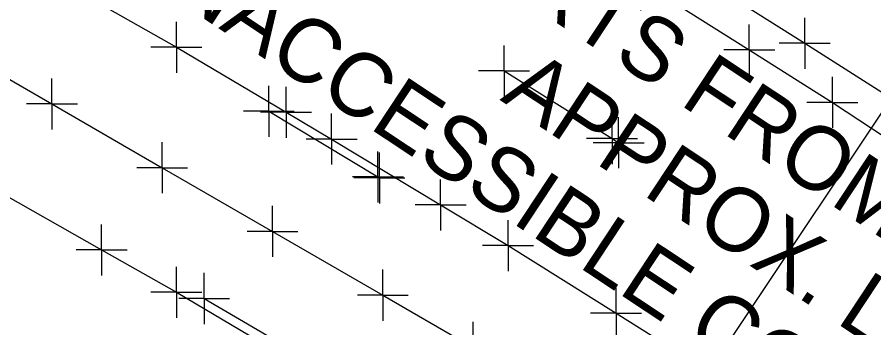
# Model space of a CAD drawing. Extents: x 0 to 1944463, y 0 to 420651.
# Drawn here: x 1942824.6 to 1942891.8, y 417789.8 to 417814.1 of the extents above; entities that cross this region are included whole.
import ezdxf

# ---------------------------------------------------------------- set-up
doc = ezdxf.new("R2010")
doc.units = 0
for name, color, linetype in [('SUR - DRG - Storm Sewer Text', 7, 'Continuous'), ('SUR - DTM - Breaklines', 7, 'Continuous'), ('SUR - DTM - Breaklines - Points - Locators', 7, 'Continuous'), ('SUR - TR-CTRL - Pavement Marking', 7, 'Continuous'), ('SUR - TR-CTRL - Pavement Marking - Points - Locators', 7, 'Continuous'), ('SUR - TRAN - Features', 7, 'Continuous'), ('SUR - UTL - Overhead Wire Crossings', 7, 'Continuous')]:
    doc.layers.add(name, color=color, linetype=linetype)

msp = doc.modelspace()

# ---------------------------------------------------------------- linework, layer by layer
at = {"layer": 'SUR - DTM - Breaklines'}
msp.add_lwpolyline([(1942706.496, 417864.602), (1942715.785, 417860.899), (1942725.074, 417857.195), (1942728.142, 417855.972), (1942737.3, 417851.955), (1942746.457, 417847.938), (1942755.615, 417843.922), (1942764.773, 417839.905), (1942767.692, 417838.624), (1942776.578, 417834.037), (1942785.464, 417829.45), (1942794.35, 417824.864), (1942803.236, 417820.277), (1942812.122, 417815.69), (1942818.635, 417812.328), (1942827.298, 417807.331), (1942835.96, 417802.335), (1942844.622, 417797.339), (1942853.285, 417792.343), (1942860.379, 417788.251), (1942868.814, 417782.88), (1942877.25, 417777.509), (1942885.685, 417772.138), (1942894.12, 417766.767)], dxfattribs=at)
at = {"layer": 'SUR - DTM - Breaklines - Points - Locators'}
for p, q in [((1942827.298, 417807.331), (1942827.298, 417809.331)), ((1942827.298, 417807.331), (1942825.298, 417807.331)), ((1942827.298, 417807.331), (1942829.298, 417807.331)), ((1942827.298, 417807.331), (1942827.298, 417805.331)), ((1942835.96, 417802.335), (1942835.96, 417804.335)), ((1942835.96, 417802.335), (1942833.96, 417802.335)), ((1942835.96, 417802.335), (1942837.96, 417802.335)), ((1942835.96, 417802.335), (1942835.96, 417800.335)), ((1942844.622, 417797.339), (1942844.622, 417799.339)), ((1942844.622, 417797.339), (1942842.622, 417797.339)), ((1942844.622, 417797.339), (1942846.622, 417797.339)), ((1942844.622, 417797.339), (1942844.622, 417795.339)), ((1942853.285, 417792.343), (1942853.285, 417794.343)), ((1942853.285, 417792.343), (1942851.285, 417792.343)), ((1942853.285, 417792.343), (1942855.285, 417792.343)), ((1942853.285, 417792.343), (1942853.285, 417790.343)), ((1942860.379, 417788.251), (1942860.379, 417790.251))]:
    msp.add_line(p, q, dxfattribs=at)
at = {"layer": 'SUR - TR-CTRL - Pavement Marking'}
for points in [[(1942743.821, 417883.68), (1942753.017, 417879.751), (1942762.213, 417875.823), (1942770.046, 417872.476), (1942779.106, 417868.245), (1942788.166, 417864.013), (1942790.281, 417863.025), (1942799.195, 417858.492), (1942808.108, 417853.959), (1942814.469, 417850.724), (1942823.271, 417845.977), (1942832.073, 417841.23), (1942837.137, 417838.5), (1942845.787, 417833.481), (1942854.436, 417828.462), (1942863.086, 417823.444), (1942865.149, 417822.246), (1942873.606, 417816.91), (1942882.063, 417811.573), (1942888.586, 417807.457), (1942896.946, 417801.969)], [(1942772.498, 417845.953), (1942781.476, 417841.549), (1942786.072, 417839.295), (1942795.028, 417834.902), (1942803.852, 417830.199), (1942805.346, 417829.403), (1942814.138, 417824.639), (1942820.568, 417821.156), (1942829.263, 417816.216), (1942837.079, 417811.776), (1942845.687, 417806.687), (1942849.257, 417804.577), (1942857.825, 417799.421), (1942863.118, 417796.235), (1942871.595, 417790.931), (1942880.073, 417785.627), (1942880.966, 417785.069), (1942889.317, 417779.568), (1942894.238, 417776.326)], [(1942765.257, 417830.796), (1942774.22, 417826.361), (1942779.617, 417823.691), (1942788.514, 417819.126), (1942792.869, 417816.891), (1942801.689, 417812.177), (1942810.508, 417807.464), (1942813.783, 417805.714), (1942822.492, 417800.801), (1942831.202, 417795.887), (1942837.075, 417792.574), (1942845.682, 417787.484), (1942854.29, 417782.394), (1942858.407, 417779.959), (1942866.964, 417774.785), (1942874.398, 417770.29), (1942882.852, 417764.949), (1942890.364, 417760.204), (1942898.733, 417754.731)], [(1942862.804, 417809.923), (1942871.281, 417804.618), (1942871.798, 417804.295)], [(1942844.332, 417806.759), (1942852.902, 417801.607), (1942853.017, 417801.538)], [(1942839.255, 417792.082), (1942847.255, 417787.394)]]:
    msp.add_lwpolyline(points, dxfattribs=at)
at = {"layer": 'SUR - TR-CTRL - Pavement Marking - Points - Locators'}
for p, q in [((1942837.079, 417811.776), (1942837.079, 417813.776)), ((1942882.063, 417811.573), (1942882.063, 417813.573)), ((1942837.079, 417811.776), (1942835.079, 417811.776)), ((1942837.079, 417811.776), (1942839.079, 417811.776)), ((1942837.079, 417811.776), (1942837.079, 417809.776)), ((1942862.804, 417809.923), (1942862.804, 417811.923)), ((1942882.063, 417811.573), (1942880.063, 417811.573)), ((1942882.063, 417811.573), (1942884.063, 417811.573)), ((1942882.063, 417811.573), (1942882.063, 417809.573)), ((1942862.804, 417809.923), (1942860.804, 417809.923)), ((1942862.804, 417809.923), (1942864.804, 417809.923)), ((1942862.804, 417809.923), (1942862.804, 417807.923)), ((1942888.586, 417807.457), (1942888.586, 417809.457)), ((1942844.332, 417806.759), (1942844.332, 417808.759)), ((1942845.687, 417806.687), (1942845.687, 417808.687)), ((1942888.586, 417807.457), (1942886.586, 417807.457)), ((1942888.586, 417807.457), (1942890.586, 417807.457)), ((1942888.586, 417807.457), (1942888.586, 417805.457)), ((1942844.332, 417806.759), (1942842.332, 417806.759)), ((1942845.687, 417806.687), (1942843.687, 417806.687)), ((1942844.332, 417806.759), (1942846.332, 417806.759)), ((1942844.332, 417806.759), (1942844.332, 417804.759)), ((1942845.687, 417806.687), (1942847.687, 417806.687)), ((1942845.687, 417806.687), (1942845.687, 417804.687)), ((1942849.257, 417804.577), (1942849.257, 417806.577)), ((1942871.281, 417804.618), (1942871.281, 417806.618)), ((1942871.798, 417804.295), (1942871.798, 417806.295)), ((1942849.257, 417804.577), (1942847.257, 417804.577)), ((1942849.257, 417804.577), (1942851.257, 417804.577)), ((1942849.257, 417804.577), (1942849.257, 417802.577)), ((1942871.281, 417804.618), (1942869.281, 417804.618)), ((1942871.798, 417804.295), (1942869.798, 417804.295)), ((1942871.281, 417804.618), (1942873.281, 417804.618)), ((1942871.281, 417804.618), (1942871.281, 417802.618)), ((1942871.798, 417804.295), (1942873.798, 417804.295)), ((1942871.798, 417804.295), (1942871.798, 417802.295)), ((1942852.902, 417801.607), (1942852.902, 417803.607)), ((1942853.017, 417801.538), (1942853.017, 417803.538)), ((1942852.902, 417801.607), (1942850.902, 417801.607)), ((1942852.902, 417801.607), (1942854.902, 417801.607)), ((1942852.902, 417801.607), (1942852.902, 417799.607)), ((1942853.017, 417801.538), (1942851.017, 417801.538)), ((1942853.017, 417801.538), (1942855.017, 417801.538)), ((1942853.017, 417801.538), (1942853.017, 417799.538)), ((1942857.825, 417799.421), (1942857.825, 417801.421)), ((1942857.825, 417799.421), (1942855.825, 417799.421)), ((1942857.825, 417799.421), (1942859.825, 417799.421)), ((1942857.825, 417799.421), (1942857.825, 417797.421)), ((1942863.118, 417796.235), (1942863.118, 417798.235)), ((1942831.202, 417795.887), (1942831.202, 417797.887)), ((1942863.118, 417796.235), (1942861.118, 417796.235)), ((1942863.118, 417796.235), (1942865.118, 417796.235)), ((1942863.118, 417796.235), (1942863.118, 417794.235)), ((1942831.202, 417795.887), (1942829.202, 417795.887)), ((1942831.202, 417795.887), (1942833.202, 417795.887)), ((1942831.202, 417795.887), (1942831.202, 417793.887)), ((1942837.075, 417792.574), (1942837.075, 417794.574)), ((1942839.255, 417792.082), (1942839.255, 417794.082)), ((1942871.595, 417790.931), (1942871.595, 417792.931)), ((1942837.075, 417792.574), (1942835.075, 417792.574)), ((1942837.075, 417792.574), (1942839.075, 417792.574)), ((1942837.075, 417792.574), (1942837.075, 417790.574)), ((1942839.255, 417792.082), (1942837.255, 417792.082)), ((1942839.255, 417792.082), (1942841.255, 417792.082)), ((1942839.255, 417792.082), (1942839.255, 417790.082)), ((1942871.595, 417790.931), (1942869.595, 417790.931)), ((1942871.595, 417790.931), (1942873.595, 417790.931)), ((1942871.595, 417790.931), (1942871.595, 417788.931))]:
    msp.add_line(p, q, dxfattribs=at)
at = {"layer": 'SUR - TRAN - Features'}
for q in [(1942886.414, 417814.085), (1942884.414, 417812.085), (1942888.414, 417812.085), (1942886.414, 417810.085)]:
    msp.add_line((1942886.414, 417812.085), q, dxfattribs=at)
msp.add_lwpolyline([(1942799.725, 417861.277), (1942808.615, 417856.696), (1942815.567, 417853.113), (1942824.359, 417848.347), (1942833.15, 417843.582), (1942833.405, 417843.443), (1942842.112, 417838.524), (1942850.818, 417833.605), (1942856.096, 417830.623), (1942864.658, 417825.457), (1942873.22, 417820.29), (1942877.962, 417817.43), (1942886.414, 417812.085), (1942894.204, 417807.16)], dxfattribs=at)
at = {"layer": 'SUR - UTL - Overhead Wire Crossings'}
msp.add_lwpolyline([(1942849.572, 417742.451), (1942957.655, 417904.238)], dxfattribs=at)

# ---------------------------------------------------------------- texts
at = {"layer": 'SUR - DRG - Storm Sewer Text'}
for s, p in [('INVERTS FROM CONST. PLANS', (1942850.783, 417824.362)), ('INACCESSIBLE COVERED JUNCTION', (1942834.765, 417816.974)), ('APPROX. LOCATION ', (1942862.43, 417807.662))]:
    msp.add_text(s, height=4.99999, rotation=326.50837, dxfattribs=at).set_placement(p)

doc.saveas('drawing.dxf')
